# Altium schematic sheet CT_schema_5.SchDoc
size 277 x 170 mm
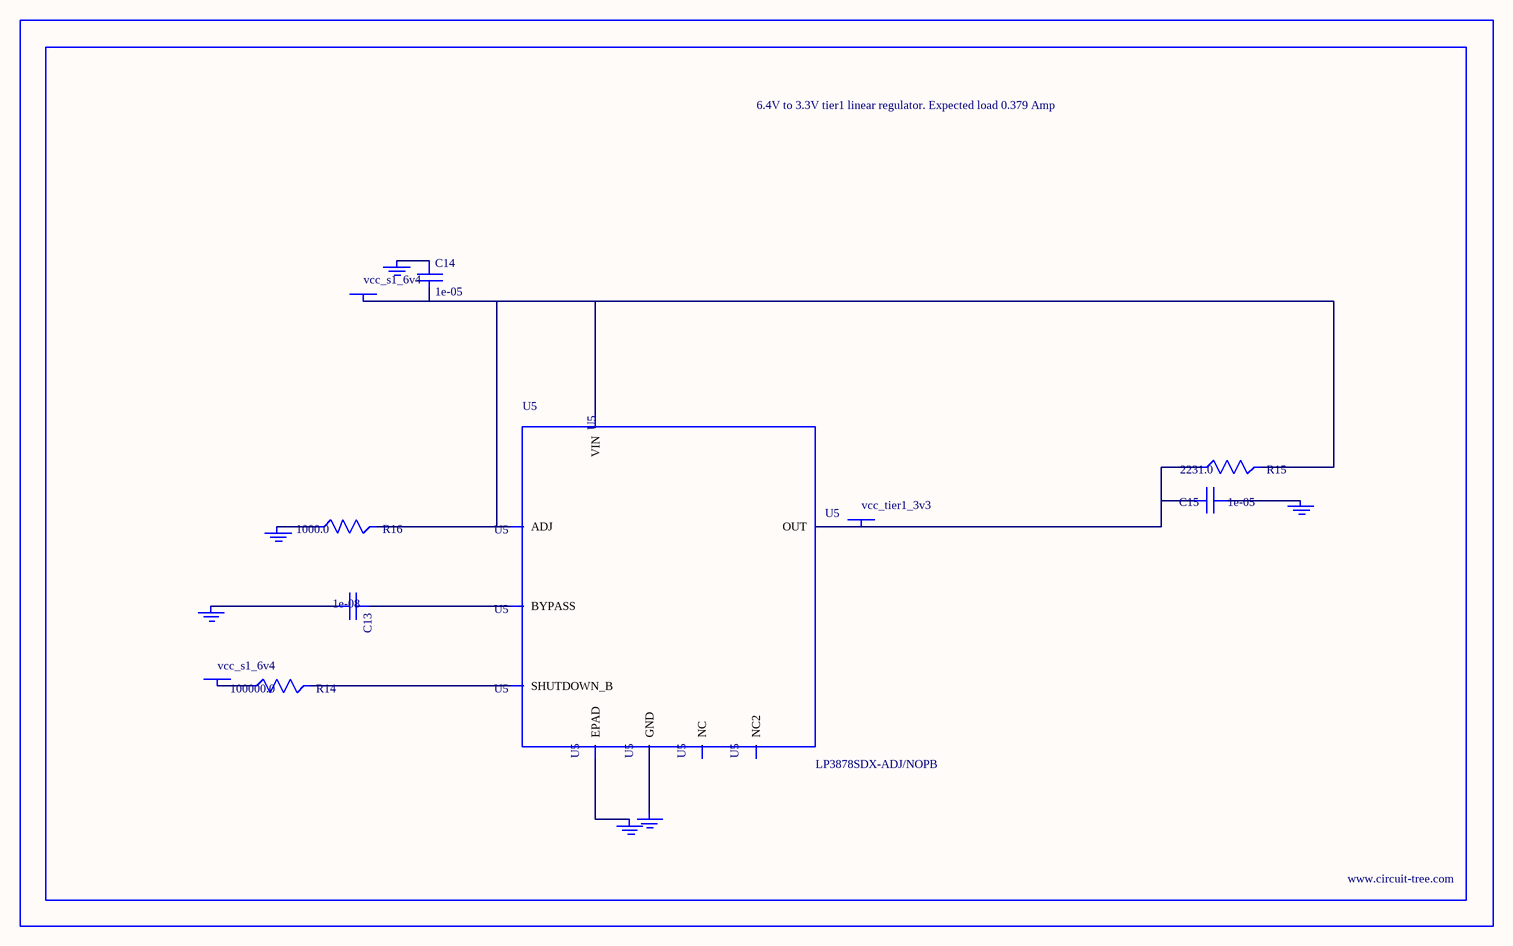
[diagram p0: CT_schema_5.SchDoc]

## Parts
BORDER4  (no value)
C13  1e-08  [C0402]
C14  1e-05  [C1206]
C15  1e-05  [C1210]
GND_INSTANCE_4_0  (no value)
GND_INSTANCE_4_1  (no value)
GND_INSTANCE_4_2  (no value)
GND_INSTANCE_4_3  (no value)
GND_INSTANCE_4_4  (no value)
GND_INSTANCE_4_5  (no value)
POWER_INSTANCE_4_0  vcc_s1_6v4
POWER_INSTANCE_4_1  vcc_s1_6v4
POWER_INSTANCE_4_2  vcc_tier1_3v3
R14  100000.0  [R0603]
R15  2231.0  [R0603]
R16  1000.0  [R0603]
U5  LP3878SDX-ADJ/NOPB  [WSON-8]

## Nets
NetC13_1: C13.1 U5.1(BYPASS)
NetC13_2: C13.2 GND_INSTANCE_4_0.0(GND)
NetC14_1: C14.1 GND_INSTANCE_4_1.0(GND)
NetC14_2: C14.2 POWER_INSTANCE_4_0.0(PWR) R15.2 R16.2 U5.4(VIN) U5.6(ADJ)
NetC15_1: C15.1 GND_INSTANCE_4_2.0(GND)
NetC15_2: C15.2 POWER_INSTANCE_4_2.0(PWR) R15.1 U5.5(OUT)
NetGND_INSTANCE_4_3_0: GND_INSTANCE_4_3.0(GND) R16.1
NetGND_INSTANCE_4_4_0: GND_INSTANCE_4_4.0(GND) U5.PAD(EPAD)
NetGND_INSTANCE_4_5_0: GND_INSTANCE_4_5.0(GND) U5.3(GND)
NetPOWER_INSTANCE_4_1_0: POWER_INSTANCE_4_1.0(PWR) R14.1
NetR14_2: R14.2 U5.8(SHUTDOWN_B)

Not connected (* = marked no-connect by the designer): U5 2(NC) 7(NC2)

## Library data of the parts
BORDER4 = BORDER_PAGE4
C13 = C0402C103K3RAC
C14 = C1206C106K3RACTU
C15 = GRM32DR61E106MA12L
GND_INSTANCE_4_0-GND_INSTANCE_4_5 = GND
POWER_INSTANCE_4_0-POWER_INSTANCE_4_2 = PWR
R14 = RC0603JR-07100KL
R15 = R15
R16 = RC0603JR-071KL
